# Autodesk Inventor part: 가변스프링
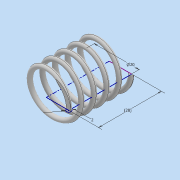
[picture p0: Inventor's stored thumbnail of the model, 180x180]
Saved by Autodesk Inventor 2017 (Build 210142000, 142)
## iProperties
Part Number: 가변스프링
Material: 일반
Document SubType Name: Modeling
Designer: mrc
Density: 1 g/cm^3
Appearance: 기본값
Author: mrc
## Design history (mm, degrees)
sketch "스케치1"
  geometry: L1 (0, 0)-(10, 0); L2 (10, 0)-(10, 28); L3 (10, 28)-(0, 28); L4 (0, 28)-(0, 0); C1 r 1 at (10, 0)
  constraints: 8 end point, 2 parallel, 1 centre point, 1 coincident, 1 horizontal, 1 perpendicular
  dimensions: "d0" = 28 distance of L1.end L2.end (derived); "d1" = 20 diameter of L2 L4; "d2" = 2 diameter of C1
feature "코일1" sketch "스케치1" pitch "d3" = 10; turns "d5" = 5; dims "d4" = 28 (= d0), "d6" = 0, angle "d7" = 90 deg, angle "d8" = 90 deg, "d9" = 0, "d10" = 0
sketch "스케치2"
  geometry: L1 (-18.58, 0)-(18.58, 0); L2 (18.58, 0)-(18.58, 28); L3 (18.58, 28)-(-18.58, 28); L4 (-18.58, 28)-(-18.58, 0); 2 further points
  constraints: 8 end point, 2 parallel, 1 coincident, 1 horizontal, 1 midpoint, 1 perpendicular
  dimensions: "d11" = 28 distance of L1.end L2.end (= d0); "d12" = 37.15926 distance of L2.end L3.end
extrude "돌출1" sketch "스케치2" stored distance "d13" = 0; taper "d14" = 0 deg
node "솔리드1"
